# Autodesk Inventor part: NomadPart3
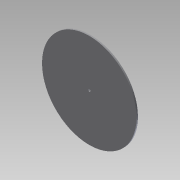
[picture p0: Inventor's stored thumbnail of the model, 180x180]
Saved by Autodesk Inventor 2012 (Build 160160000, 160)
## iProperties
Created: 2012-10
Part Number: NomadPart3
Material: Default
Document SubType Name: Modeling
Designer: TechShop Member
Density: 1 g/cm^3
Author: TechShop Member
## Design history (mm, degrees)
sketch "Sketch1"
  geometry: C1 r 105.792 at (0, 0); 1 further point
  constraints: 1 centre point, 1 coincident
  dimensions: "d0" = 211.58454 diameter of C1
extrude "Extrusion1" new body sketch "Sketch1" distance "d1" = 3.175; taper "d2" = 0 deg
sketch "Sketch2"
  geometry: C1 r 105.792 at (0, 0) reference; 1 further point
  constraints: 1 coincident
hole "Hole1" sketch "Sketch2" at (0, 0) diameter "d3" = 5.207; stored, may be unused: countersink angle "d7" = 82 deg, drill point angle "d9" = 118 deg; dims "d4" = 19.05, "d5" = 9.525, "d6" = 6.35, "d8" = 25.4
body "Solid1"
